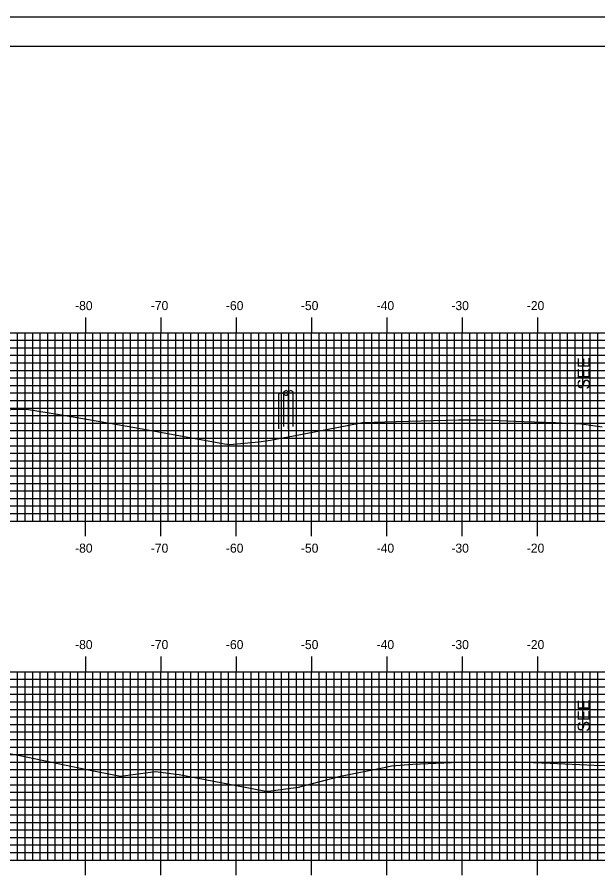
# Model space of a CAD drawing. Extents: x 1685979 to 1686323, y 461260 to 461480.
# Drawn here: x 1686056.2 to 1686133.3, y 461365.6 to 461480 of the extents above; entities that cross this region are included whole.
import ezdxf

# ---------------------------------------------------------------- set-up
doc = ezdxf.new("R2010")
doc.units = 0
for name, color, linetype in [('ANNOTATION', 7, 'Continuous'), ('BORDER', 7, 'Continuous'), ('D_Roadway_Centerline', 7, 'Continuous'), ('H_V ANNOTATION', 7, 'Continuous'), ('M_Roadway_Centerline', 7, 'Continuous'), ('M_Utilities_Pole_StreetLight', 7, 'Continuous'), ('MAJOR', 7, 'Continuous'), ('MINOR', 7, 'Continuous'), ('PLOT BOUNDARY', 7, 'Continuous'), ('S_Roadway_Centerline', 7, 'Continuous'), ('S_Utilities_Pole_StreetLight', 7, 'Continuous')]:
    doc.layers.add(name, color=color, linetype=linetype)

msp = doc.modelspace()

# ---------------------------------------------------------------- linework, layer by layer
at = {"layer": 'BORDER'}
msp.add_lwpolyline([(1685995.66, 461266.07), (1686315.66, 461266.07), (1686315.66, 461476.07), (1685995.66, 461476.07)], close=True, dxfattribs=at)
at = {"layer": 'M_Utilities_Pole_StreetLight'}
for p, q in [((1686090.95, 461429.95), (1686091.11, 461430.06)), ((1686090.95, 461425.33), (1686090.95, 461429.95)), ((1686091.42, 461430.06), (1686091.58, 461429.95)), ((1686091.74, 461430.06), (1686091.58, 461429.95)), ((1686091.58, 461429.95), (1686091.74, 461429.84)), ((1686092.2, 461429.95), (1686092.05, 461430.06)), ((1686092.05, 461429.84), (1686092.2, 461429.95)), ((1686092.2, 461425.33), (1686092.2, 461429.95))]:
    msp.add_line(p, q, dxfattribs=at)
for centre, start, end in [((1686091.27, 461429.84), 90, 125.2644), ((1686091.27, 461429.84), 54.7356, 90), ((1686091.89, 461429.84), 90, 125.2644), ((1686091.89, 461430.06), 234.7356, 270), ((1686091.89, 461429.84), 54.7356, 90), ((1686091.89, 461430.06), 270, 305.2644)]:
    msp.add_arc(centre, 0.271, start, end, dxfattribs=at)
at = {"layer": 'MAJOR'}
for p, q in [((1686065.26, 461440.08), (1686065.26, 461438.07)), ((1686075.26, 461440.08), (1686075.26, 461438.07)), ((1686085.26, 461440.08), (1686085.26, 461438.07)), ((1686095.26, 461440.08), (1686095.26, 461438.07)), ((1686105.26, 461440.08), (1686105.26, 461438.07)), ((1686115.26, 461440.08), (1686115.26, 461438.07)), ((1686125.26, 461440.08), (1686125.26, 461438.07)), ((1686005.26, 461438.07), (1686285.26, 461438.07)), ((1686005.26, 461438.07), (1686285.26, 461438.07)), ((1686065.26, 461413.07), (1686065.26, 461438.07)), ((1686075.26, 461413.07), (1686075.26, 461438.07)), ((1686085.26, 461413.07), (1686085.26, 461438.07)), ((1686095.26, 461413.07), (1686095.26, 461438.07)), ((1686105.26, 461413.07), (1686105.26, 461438.07)), ((1686115.26, 461413.07), (1686115.26, 461438.07)), ((1686125.26, 461413.07), (1686125.26, 461438.07)), ((1686005.26, 461433.07), (1686285.26, 461433.07)), ((1686005.26, 461428.07), (1686285.26, 461428.07)), ((1686005.26, 461423.07), (1686285.26, 461423.07)), ((1686005.26, 461418.07), (1686285.26, 461418.07)), ((1686005.26, 461413.07), (1686285.26, 461413.07)), ((1686005.26, 461413.07), (1686285.26, 461413.07)), ((1686065.26, 461411.07), (1686065.26, 461413.07)), ((1686075.26, 461411.07), (1686075.26, 461413.07)), ((1686085.26, 461411.07), (1686085.26, 461413.07)), ((1686095.26, 461411.07), (1686095.26, 461413.07)), ((1686105.26, 461411.07), (1686105.26, 461413.07)), ((1686115.26, 461411.07), (1686115.26, 461413.07)), ((1686125.26, 461411.07), (1686125.26, 461413.07)), ((1686065.26, 461395.08), (1686065.26, 461393.07)), ((1686075.26, 461395.08), (1686075.26, 461393.07)), ((1686085.26, 461395.08), (1686085.26, 461393.07)), ((1686095.26, 461395.08), (1686095.26, 461393.07)), ((1686105.26, 461395.08), (1686105.26, 461393.07)), ((1686115.26, 461395.08), (1686115.26, 461393.07)), ((1686125.26, 461395.08), (1686125.26, 461393.07)), ((1686005.26, 461393.07), (1686285.26, 461393.07)), ((1686005.26, 461393.07), (1686285.26, 461393.07)), ((1686065.26, 461368.07), (1686065.26, 461393.07)), ((1686075.26, 461368.07), (1686075.26, 461393.07)), ((1686085.26, 461368.07), (1686085.26, 461393.07)), ((1686095.26, 461368.07), (1686095.26, 461393.07)), ((1686105.26, 461368.07), (1686105.26, 461393.07)), ((1686115.26, 461368.07), (1686115.26, 461393.07)), ((1686125.26, 461368.07), (1686125.26, 461393.07)), ((1686005.26, 461388.07), (1686285.26, 461388.07)), ((1686005.26, 461383.07), (1686285.26, 461383.07)), ((1686005.26, 461378.07), (1686285.26, 461378.07)), ((1686005.26, 461373.07), (1686285.26, 461373.07)), ((1686005.26, 461368.07), (1686285.26, 461368.07)), ((1686005.26, 461368.07), (1686285.26, 461368.07)), ((1686065.26, 461366.07), (1686065.26, 461368.07)), ((1686075.26, 461366.07), (1686075.26, 461368.07)), ((1686085.26, 461366.07), (1686085.26, 461368.07)), ((1686095.26, 461366.07), (1686095.26, 461368.07)), ((1686105.26, 461366.07), (1686105.26, 461368.07)), ((1686115.26, 461366.07), (1686115.26, 461368.07)), ((1686125.26, 461366.07), (1686125.26, 461368.07))]:
    msp.add_line(p, q, dxfattribs=at)
at = {"layer": 'MINOR'}
for p, q in [((1686005.26, 461437.07), (1686285.26, 461437.07)), ((1686056.26, 461413.07), (1686056.26, 461438.07)), ((1686057.26, 461413.07), (1686057.26, 461438.07)), ((1686058.26, 461413.07), (1686058.26, 461438.07)), ((1686059.26, 461413.07), (1686059.26, 461438.07)), ((1686060.26, 461413.07), (1686060.26, 461438.07)), ((1686061.26, 461413.07), (1686061.26, 461438.07)), ((1686062.26, 461413.07), (1686062.26, 461438.07)), ((1686063.26, 461413.07), (1686063.26, 461438.07)), ((1686064.26, 461413.07), (1686064.26, 461438.07)), ((1686066.26, 461413.07), (1686066.26, 461438.07)), ((1686067.26, 461413.07), (1686067.26, 461438.07)), ((1686068.26, 461413.07), (1686068.26, 461438.07)), ((1686069.26, 461413.07), (1686069.26, 461438.07)), ((1686070.26, 461413.07), (1686070.26, 461438.07)), ((1686071.26, 461413.07), (1686071.26, 461438.07)), ((1686072.26, 461413.07), (1686072.26, 461438.07)), ((1686073.26, 461413.07), (1686073.26, 461438.07)), ((1686074.26, 461413.07), (1686074.26, 461438.07)), ((1686076.26, 461413.07), (1686076.26, 461438.07)), ((1686077.26, 461413.07), (1686077.26, 461438.07)), ((1686078.26, 461413.07), (1686078.26, 461438.07)), ((1686079.26, 461413.07), (1686079.26, 461438.07)), ((1686080.26, 461413.07), (1686080.26, 461438.07)), ((1686081.26, 461413.07), (1686081.26, 461438.07)), ((1686082.26, 461413.07), (1686082.26, 461438.07)), ((1686083.26, 461413.07), (1686083.26, 461438.07)), ((1686084.26, 461413.07), (1686084.26, 461438.07)), ((1686086.26, 461413.07), (1686086.26, 461438.07)), ((1686087.26, 461413.07), (1686087.26, 461438.07)), ((1686088.26, 461413.07), (1686088.26, 461438.07)), ((1686089.26, 461413.07), (1686089.26, 461438.07)), ((1686090.26, 461413.07), (1686090.26, 461438.07)), ((1686091.26, 461413.07), (1686091.26, 461438.07)), ((1686092.26, 461413.07), (1686092.26, 461438.07)), ((1686093.26, 461413.07), (1686093.26, 461438.07)), ((1686094.26, 461413.07), (1686094.26, 461438.07)), ((1686096.26, 461413.07), (1686096.26, 461438.07)), ((1686097.26, 461413.07), (1686097.26, 461438.07)), ((1686098.26, 461413.07), (1686098.26, 461438.07)), ((1686099.26, 461413.07), (1686099.26, 461438.07)), ((1686100.26, 461413.07), (1686100.26, 461438.07)), ((1686101.26, 461413.07), (1686101.26, 461438.07)), ((1686102.26, 461413.07), (1686102.26, 461438.07)), ((1686103.26, 461413.07), (1686103.26, 461438.07)), ((1686104.26, 461413.07), (1686104.26, 461438.07)), ((1686106.26, 461413.07), (1686106.26, 461438.07)), ((1686107.26, 461413.07), (1686107.26, 461438.07)), ((1686108.26, 461413.07), (1686108.26, 461438.07)), ((1686109.26, 461413.07), (1686109.26, 461438.07)), ((1686110.26, 461413.07), (1686110.26, 461438.07)), ((1686111.26, 461413.07), (1686111.26, 461438.07)), ((1686112.26, 461413.07), (1686112.26, 461438.07)), ((1686113.26, 461413.07), (1686113.26, 461438.07)), ((1686114.26, 461413.07), (1686114.26, 461438.07)), ((1686116.26, 461413.07), (1686116.26, 461438.07)), ((1686117.26, 461413.07), (1686117.26, 461438.07)), ((1686118.26, 461413.07), (1686118.26, 461438.07)), ((1686119.26, 461413.07), (1686119.26, 461438.07)), ((1686120.26, 461413.07), (1686120.26, 461438.07)), ((1686121.26, 461413.07), (1686121.26, 461438.07)), ((1686122.26, 461413.07), (1686122.26, 461438.07)), ((1686123.26, 461413.07), (1686123.26, 461438.07)), ((1686124.26, 461413.07), (1686124.26, 461438.07)), ((1686126.26, 461413.07), (1686126.26, 461438.07)), ((1686127.26, 461413.07), (1686127.26, 461438.07)), ((1686128.26, 461413.07), (1686128.26, 461438.07)), ((1686129.26, 461413.07), (1686129.26, 461438.07)), ((1686130.26, 461413.07), (1686130.26, 461438.07)), ((1686131.26, 461413.07), (1686131.26, 461438.07)), ((1686132.26, 461413.07), (1686132.26, 461438.07)), ((1686133.26, 461413.07), (1686133.26, 461438.07)), ((1686005.26, 461436.07), (1686285.26, 461436.07)), ((1686005.26, 461435.07), (1686285.26, 461435.07)), ((1686005.26, 461434.07), (1686285.26, 461434.07)), ((1686005.26, 461432.07), (1686285.26, 461432.07)), ((1686005.26, 461431.07), (1686285.26, 461431.07)), ((1686005.26, 461430.07), (1686285.26, 461430.07)), ((1686005.26, 461429.07), (1686285.26, 461429.07)), ((1686005.26, 461427.07), (1686285.26, 461427.07)), ((1686005.26, 461426.07), (1686285.26, 461426.07)), ((1686005.26, 461425.07), (1686285.26, 461425.07)), ((1686005.26, 461424.07), (1686285.26, 461424.07)), ((1686005.26, 461422.07), (1686285.26, 461422.07)), ((1686005.26, 461421.07), (1686285.26, 461421.07)), ((1686005.26, 461420.07), (1686285.26, 461420.07)), ((1686005.26, 461419.07), (1686285.26, 461419.07)), ((1686005.26, 461417.07), (1686285.26, 461417.07)), ((1686005.26, 461416.07), (1686285.26, 461416.07)), ((1686005.26, 461415.07), (1686285.26, 461415.07)), ((1686005.26, 461414.07), (1686285.26, 461414.07)), ((1686056.26, 461368.07), (1686056.26, 461393.07)), ((1686057.26, 461368.07), (1686057.26, 461393.07)), ((1686058.26, 461368.07), (1686058.26, 461393.07)), ((1686059.26, 461368.07), (1686059.26, 461393.07)), ((1686060.26, 461368.07), (1686060.26, 461393.07)), ((1686061.26, 461368.07), (1686061.26, 461393.07)), ((1686062.26, 461368.07), (1686062.26, 461393.07)), ((1686063.26, 461368.07), (1686063.26, 461393.07)), ((1686064.26, 461368.07), (1686064.26, 461393.07)), ((1686066.26, 461368.07), (1686066.26, 461393.07)), ((1686067.26, 461368.07), (1686067.26, 461393.07)), ((1686068.26, 461368.07), (1686068.26, 461393.07)), ((1686069.26, 461368.07), (1686069.26, 461393.07)), ((1686070.26, 461368.07), (1686070.26, 461393.07)), ((1686071.26, 461368.07), (1686071.26, 461393.07)), ((1686072.26, 461368.07), (1686072.26, 461393.07)), ((1686073.26, 461368.07), (1686073.26, 461393.07)), ((1686074.26, 461368.07), (1686074.26, 461393.07)), ((1686076.26, 461368.07), (1686076.26, 461393.07)), ((1686077.26, 461368.07), (1686077.26, 461393.07)), ((1686078.26, 461368.07), (1686078.26, 461393.07)), ((1686079.26, 461368.07), (1686079.26, 461393.07)), ((1686080.26, 461368.07), (1686080.26, 461393.07)), ((1686081.26, 461368.07), (1686081.26, 461393.07)), ((1686082.26, 461368.07), (1686082.26, 461393.07)), ((1686083.26, 461368.07), (1686083.26, 461393.07)), ((1686084.26, 461368.07), (1686084.26, 461393.07)), ((1686086.26, 461368.07), (1686086.26, 461393.07)), ((1686087.26, 461368.07), (1686087.26, 461393.07)), ((1686088.26, 461368.07), (1686088.26, 461393.07)), ((1686089.26, 461368.07), (1686089.26, 461393.07)), ((1686090.26, 461368.07), (1686090.26, 461393.07)), ((1686091.26, 461368.07), (1686091.26, 461393.07)), ((1686092.26, 461368.07), (1686092.26, 461393.07)), ((1686093.26, 461368.07), (1686093.26, 461393.07)), ((1686094.26, 461368.07), (1686094.26, 461393.07)), ((1686096.26, 461368.07), (1686096.26, 461393.07)), ((1686097.26, 461368.07), (1686097.26, 461393.07)), ((1686098.26, 461368.07), (1686098.26, 461393.07)), ((1686099.26, 461368.07), (1686099.26, 461393.07)), ((1686100.26, 461368.07), (1686100.26, 461393.07)), ((1686101.26, 461368.07), (1686101.26, 461393.07)), ((1686102.26, 461368.07), (1686102.26, 461393.07)), ((1686103.26, 461368.07), (1686103.26, 461393.07)), ((1686104.26, 461368.07), (1686104.26, 461393.07)), ((1686106.26, 461368.07), (1686106.26, 461393.07)), ((1686107.26, 461368.07), (1686107.26, 461393.07)), ((1686108.26, 461368.07), (1686108.26, 461393.07)), ((1686109.26, 461368.07), (1686109.26, 461393.07)), ((1686110.26, 461368.07), (1686110.26, 461393.07)), ((1686111.26, 461368.07), (1686111.26, 461393.07)), ((1686112.26, 461368.07), (1686112.26, 461393.07)), ((1686113.26, 461368.07), (1686113.26, 461393.07)), ((1686114.26, 461368.07), (1686114.26, 461393.07)), ((1686116.26, 461368.07), (1686116.26, 461393.07)), ((1686117.26, 461368.07), (1686117.26, 461393.07)), ((1686118.26, 461368.07), (1686118.26, 461393.07)), ((1686119.26, 461368.07), (1686119.26, 461393.07)), ((1686120.26, 461368.07), (1686120.26, 461393.07)), ((1686121.26, 461368.07), (1686121.26, 461393.07)), ((1686122.26, 461368.07), (1686122.26, 461393.07)), ((1686123.26, 461368.07), (1686123.26, 461393.07)), ((1686124.26, 461368.07), (1686124.26, 461393.07)), ((1686126.26, 461368.07), (1686126.26, 461393.07)), ((1686127.26, 461368.07), (1686127.26, 461393.07)), ((1686128.26, 461368.07), (1686128.26, 461393.07)), ((1686129.26, 461368.07), (1686129.26, 461393.07)), ((1686130.26, 461368.07), (1686130.26, 461393.07)), ((1686131.26, 461368.07), (1686131.26, 461393.07)), ((1686132.26, 461368.07), (1686132.26, 461393.07)), ((1686133.26, 461368.07), (1686133.26, 461393.07)), ((1686005.26, 461392.07), (1686285.26, 461392.07)), ((1686005.26, 461391.07), (1686285.26, 461391.07)), ((1686005.26, 461390.07), (1686285.26, 461390.07)), ((1686005.26, 461389.07), (1686285.26, 461389.07)), ((1686005.26, 461387.07), (1686285.26, 461387.07)), ((1686005.26, 461386.07), (1686285.26, 461386.07)), ((1686005.26, 461385.07), (1686285.26, 461385.07)), ((1686005.26, 461384.07), (1686285.26, 461384.07)), ((1686005.26, 461382.07), (1686285.26, 461382.07)), ((1686005.26, 461381.07), (1686285.26, 461381.07)), ((1686005.26, 461380.07), (1686285.26, 461380.07)), ((1686005.26, 461379.07), (1686285.26, 461379.07)), ((1686005.26, 461377.07), (1686285.26, 461377.07)), ((1686005.26, 461376.07), (1686285.26, 461376.07)), ((1686005.26, 461375.07), (1686285.26, 461375.07)), ((1686005.26, 461374.07), (1686285.26, 461374.07)), ((1686005.26, 461372.07), (1686285.26, 461372.07)), ((1686005.26, 461371.07), (1686285.26, 461371.07)), ((1686005.26, 461370.07), (1686285.26, 461370.07)), ((1686005.26, 461369.07), (1686285.26, 461369.07))]:
    msp.add_line(p, q, dxfattribs=at)
at = {"layer": 'PLOT BOUNDARY'}
msp.add_lwpolyline([(1685979.47, 461259.95), (1686319.47, 461259.95), (1686319.47, 461479.95), (1685979.47, 461479.95)], close=True, dxfattribs=at)
at = {"layer": 'S_Roadway_Centerline'}
for points in [[(1686053.29, 461427.84), (1686057.45, 461427.93), (1686062.1, 461427.19), (1686071.8, 461425.51), (1686083.71, 461423.33), (1686084.43, 461423.23), (1686088.28, 461423.6), (1686089.83, 461423.79), (1686094.5, 461424.7), (1686101.83, 461426.11), (1686102.01, 461426.16), (1686106.48, 461426.27), (1686114.78, 461426.52), (1686118.03, 461426.51), (1686119.1, 461426.46), (1686123.46, 461426.28), (1686127.66, 461426.15), (1686131.08, 461425.99), (1686133.83, 461425.56)], [(1686053.68, 461382.48), (1686056.57, 461381.96), (1686065.45, 461380.09), (1686069.9, 461379.18), (1686074.58, 461379.81), (1686076.94, 461379.52), (1686077.69, 461379.42), (1686088.99, 461377.24), (1686089.53, 461377.2), (1686093.54, 461377.75), (1686099.13, 461379.18), (1686104.9, 461380.37), (1686105.9, 461380.56), (1686108.69, 461380.78), (1686114.86, 461381.04), (1686122.4, 461381.1), (1686122.47, 461381.1), (1686126.93, 461380.91), (1686132.77, 461380.68), (1686135.57, 461380.55)]]:
    msp.add_lwpolyline(points, dxfattribs=at)
at = {"layer": 'S_Utilities_Pole_StreetLight'}
for p, q in [((1686091.58, 461425.6), (1686091.57, 461430.22)), ((1686091.58, 461425.6), (1686091.57, 461430.22)), ((1686091.58, 461430.22), (1686091.73, 461430.33)), ((1686091.58, 461430.22), (1686091.73, 461430.33)), ((1686092.04, 461430.33), (1686092.2, 461430.22)), ((1686092.04, 461430.33), (1686092.2, 461430.22)), ((1686092.36, 461430.33), (1686092.2, 461430.22)), ((1686092.36, 461430.33), (1686092.2, 461430.22)), ((1686092.2, 461430.22), (1686092.36, 461430.11)), ((1686092.2, 461430.22), (1686092.36, 461430.11)), ((1686092.83, 461430.22), (1686092.67, 461430.33)), ((1686092.83, 461430.22), (1686092.67, 461430.33)), ((1686092.67, 461430.11), (1686092.83, 461430.22)), ((1686092.67, 461430.11), (1686092.83, 461430.22)), ((1686092.83, 461425.6), (1686092.82, 461430.22)), ((1686092.83, 461425.6), (1686092.82, 461430.22))]:
    msp.add_line(p, q, dxfattribs=at)
for centre, start, end in [((1686091.89, 461430.11), 90, 125.2644), ((1686091.89, 461430.11), 90, 125.2644), ((1686091.89, 461430.11), 54.7356, 90), ((1686091.89, 461430.11), 54.7356, 90), ((1686092.51, 461430.11), 90, 125.2644), ((1686092.51, 461430.11), 90, 125.2644), ((1686092.51, 461430.11), 54.7356, 90), ((1686092.51, 461430.11), 54.7356, 90), ((1686092.51, 461430.33), 234.7356, 270), ((1686092.51, 461430.33), 234.7356, 270), ((1686092.51, 461430.33), 270, 305.2644), ((1686092.51, 461430.33), 270, 305.2644)]:
    msp.add_arc(centre, 0.271, start, end, dxfattribs=at)

# ---------------------------------------------------------------- texts
at = {"layer": 'ANNOTATION'}
for p in [(1686132.19, 461430.53), (1686132.19, 461385.09)]:
    msp.add_text('SEE', height=1.6, rotation=90, dxfattribs=at).set_placement(p)
at = {"layer": 'D_Roadway_Centerline'}
for s, p in [('C', (1686115.91, 461380.43)), ('L', (1686115.92, 461380.42)), ('C', (1686116.51, 461380.39)), ('L', (1686116.52, 461380.38))]:
    msp.add_text(s, height=0.0146, dxfattribs=at).set_placement(p)
at = {"layer": 'H_V ANNOTATION'}
for s, p in [('-80', (1686063.89, 461441.07)), ('-70', (1686073.94, 461441.07)), ('-60', (1686083.91, 461441.07)), ('-50', (1686093.86, 461441.07)), ('-40', (1686103.91, 461441.07)), ('-30', (1686113.83, 461441.07)), ('-20', (1686123.84, 461441.07)), ('-80', (1686063.89, 461408.87)), ('-70', (1686073.94, 461408.87)), ('-60', (1686083.91, 461408.87)), ('-50', (1686093.86, 461408.87)), ('-40', (1686103.91, 461408.87)), ('-30', (1686113.83, 461408.87)), ('-20', (1686123.84, 461408.87)), ('-80', (1686063.89, 461396.07)), ('-70', (1686073.94, 461396.07)), ('-60', (1686083.91, 461396.07)), ('-50', (1686093.86, 461396.07)), ('-40', (1686103.91, 461396.07)), ('-30', (1686113.83, 461396.07)), ('-20', (1686123.84, 461396.07))]:
    msp.add_text(s, height=1.2, dxfattribs=at).set_placement(p)
at = {"layer": 'M_Roadway_Centerline'}
for s, p in [('C', (1686118.02, 461426.51)), ('L', (1686118.03, 461426.5)), ('C', (1686122.46, 461381.1)), ('L', (1686122.47, 461381.09))]:
    msp.add_text(s, height=0.0146, dxfattribs=at).set_placement(p)

doc.saveas('drawing.dxf')
